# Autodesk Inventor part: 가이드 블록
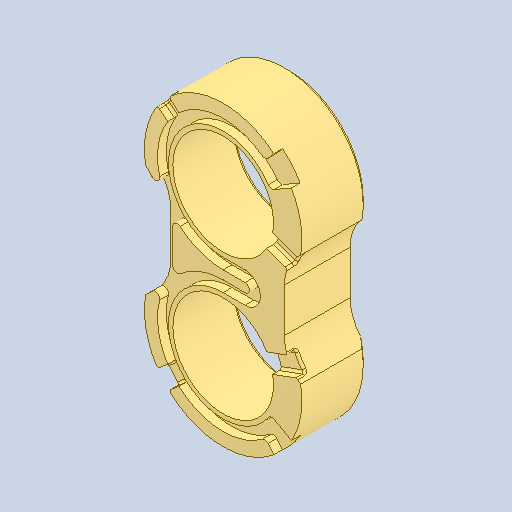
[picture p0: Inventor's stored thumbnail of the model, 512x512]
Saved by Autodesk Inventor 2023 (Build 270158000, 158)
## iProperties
Created: 2025-10
Part Number: 가이드 블록
Material: 강철, 주조
Document SubType Name: Modeling
Designer: home
Density: 7.85 g/cm^3
Appearance: 기본값
Author: jhkim
Sending System: Autodesk Inventor 2026
Preprocessor: ST-DEVELOPER v20.1
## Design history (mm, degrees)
feature "솔리드1"
node "솔리드2"
